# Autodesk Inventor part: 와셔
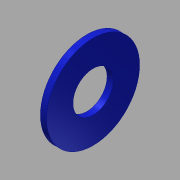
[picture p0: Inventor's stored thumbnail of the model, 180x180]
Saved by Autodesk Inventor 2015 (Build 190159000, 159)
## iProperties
Created: 2015-12
Part Number: 와셔
Material: 스테인리스강
Document SubType Name: Modeling
Designer: mduedu
Density: 8.08 g/cm^3
Appearance: 파란색 - 벽 페인트 - 광택
Author: mduedu
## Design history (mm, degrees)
sketch "스케치1"
  geometry: C1 r 3.25 at (0, 0); C2 r 7.5 at (0, 0); 1 further point
  constraints: 2 centre point, 2 coincident
  dimensions: "d0" = 6.5 diameter of C1; "d1" = 15 diameter of C2
extrude "돌출1" new body sketch "스케치1" stored distance "d2" = 1; taper "d3" = 0 deg
node "솔리드1"
